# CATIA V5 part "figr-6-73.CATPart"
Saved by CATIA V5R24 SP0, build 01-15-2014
Part number: Part2
Bounding box of the stored display mesh (mm): x -37.886 to 37.886, y -61.415 to 61.415, z 0 to 29
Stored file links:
  D:\KAVITA\CATIA V5-6R2014 Project_ Kavita\CATIA V5-6R2014_partfiles\Partfiles\c06_catia_v5-6r2014_prt\figr-6-73.CATPart
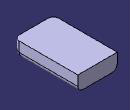
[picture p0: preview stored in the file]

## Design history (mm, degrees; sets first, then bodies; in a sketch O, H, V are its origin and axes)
Body1 (main body)
  Sketch1 on xy-plane, origin (0, 0, 0), H (1, 0, 0), V (0, 1, 0)
    line L1 (37.8862, 61.4155) -> (37.8862, -61.4155)
    line L2 (37.8862, -61.4155) -> (-37.8862, -61.4155)
    line L3 (-37.8862, -61.4155) -> (-37.8862, 61.4155)
    line L4 (-37.8862, 61.4155) -> (37.8862, 61.4155)
    vertical: L1 V, L3 V
    horizontal: L2 H, L4 H
    equidistance: L1 L3 O, L2 L4 O
  Pad1: profile Sketch1, direction (0, 0, 1), length 29
  Fillet1: radius 10, on edge [face of Pad1 | face of Pad1] (x5)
